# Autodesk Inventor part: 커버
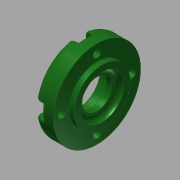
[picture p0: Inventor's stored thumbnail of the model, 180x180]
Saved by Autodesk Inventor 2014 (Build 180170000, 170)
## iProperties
Created: 2015-11
Part Number: 커버
Material: 알루미늄 6061
Document SubType Name: Modeling
Designer: mduedu
Density: 1 g/cm^3
Appearance: Smooth - Dark Forest Green
Author: mduedu
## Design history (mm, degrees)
sketch "스케치1"
  geometry: L1 (-7, 0)-(7, 0); L2 (-7, 0)-(-7, 25); L3 (-7, 25)-(4, 25); L4 (4, 25)-(4, 16); L5 (4, 16)-(7, 16); L6 (7, 16)-(7, 0); 2 further points
  constraints: 12 end point, 3 perpendicular, 2 parallel, 1 coincident, 1 horizontal, 1 midpoint
  dimensions: "d0" = 14 distance of L1.start L1.end; "d1" = 50 diameter of L3 L1; "d2" = 3 distance of L4.end L5.end; "d3" = 32 diameter of L5 L1
revolve "회전1" sketch "스케치1" stored, may be unused: angle "d4" = 90 deg
hole "구멍1" diameter "d7" = 25; stored, may be unused: countersink angle "d11" = 90 deg, drill point angle "d13" = 0 deg; dims "d5" = 10, "d6" = 10, "d8" = 6, "d9" = 4, "d10" = 2, "d12" = 3
hole "구멍2" diameter "d16" = 25; stored, may be unused: countersink angle "d20" = 90 deg, drill point angle "d22" = 0 deg; dims "d17" = 6, "d18" = 4, "d19" = 2, "d21" = 7.7, "d58" = 10, "d59" = 10
hole "구멍3" diameter "d25" = 17; stored, may be unused: countersink angle "d29" = 90 deg, drill point angle "d31" = 0 deg; dims "d23" = 10, "d24" = 10, "d26" = 6, "d27" = 4, "d28" = 2, "d30" = 4.2
chamfer "모따기1" distance "d32" = 0.6; stored, may be unused: second distance "d33" = 2, angle "d34" = 30 deg
fillet "모깎기1" dims "d35" = 0.3
fillet "모깎기2" dims "d36" = 3
fillet "모깎기3" dims "d37" = 3
fillet "모깎기4" dims "d38" = 0.3
sketch "스케치2" dims "d39" = 40
  geometry: 6 further points
  constraints: 2 vertical alignment, 1 coincident, 7 other
  dimensions: "d42" = 360 deg dimension on point (0, 0) point (0, 20) (derived)
sketch "스케치3"
  geometry: 4 further points
hole "구멍4" sketch "스케치3" at (-20, 0), (0, -20), (20, 0), (0, 20) diameter "d44" = 4.5; stored, may be unused: countersink angle "d48" = 90 deg, drill point angle "d50" = 0 deg; dims "d45" = 6, "d46" = 8, "d47" = 4.6, "d49" = 8
sketch "스케치4"
  geometry: L1 (-4, 0)-(-4, -4.678); L2 (4, 0)-(4, -4.678); A1 r 4 centre (0, 0) between (3.621, -1.7) and (-3.621, -1.7) reference; A2 r 25 centre (0, 20) between (-4, -4.678) and (4, -4.678) reference; 1 further point
  constraints: 4 end point, 4 point on circle, 2 tangent, 1 parallel, 1 vertical
extrude "돌출1" cut sketch "스케치4" stored distance "d51" = 0; taper "d52" = 0 deg
fillet "모깎기5" dims "d56" = 0.3
fillet "모깎기6" dims "d57" = 1
node "솔리드1"
pattern_circular "원형 패턴1" dims angle "d54" = 360 deg
